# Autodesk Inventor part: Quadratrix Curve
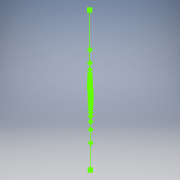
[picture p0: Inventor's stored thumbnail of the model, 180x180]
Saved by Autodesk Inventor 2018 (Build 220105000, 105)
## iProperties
Created: 2008-02
Part Number: Quadratrix Curve
Document SubType Name: Modeling
Designer: Autodesk, Inc.
Density: 1 g/cm^3
Material: Generic
Appearance: Default
Author: Autodesk, Inc.
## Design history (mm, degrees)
sketch "Sketch1"
  geometry: 298 further points
  constraints: 298 other
